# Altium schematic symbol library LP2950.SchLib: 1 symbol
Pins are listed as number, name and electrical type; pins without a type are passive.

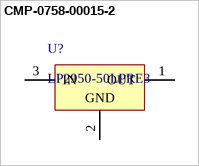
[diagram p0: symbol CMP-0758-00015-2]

## CMP-0758-00015-2
designator U?, comment LP2950-50LPRE3
Single Output LDO, 100 mA, Fixed 5 V Output, 5.4 to 30 V Input, 3-Pin TO-92 (LP), RoHS, Tape and Reel; Manufacturer: Texas Instruments; Output Capacitor Type: Non-Ceramic; Rating: Catalog; Vout (Min) (V): 4.95; Fixed Output Options (V): 5; Output Options: Fixed Output; Accuracy (%): 1.4; Vin (Max) (V): 30; Vin (Min) (V): 5.4; Vdo (Typ) (mV): 380; Vout (Max) (V): 5.05; Iq (Typ) (mA): 0.075; Iout (Max) (A): 0.1
footprint LP0003A (TO, Flat Index; 3 In-Line, Formed Axial Leads; Body Dia. 4.8mm; Leads 0.56 x 0.41 mm (max))
pins: 1 OUT (power), 2 GND (power), 3 IN (power)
